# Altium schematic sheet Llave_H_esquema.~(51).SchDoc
size A4
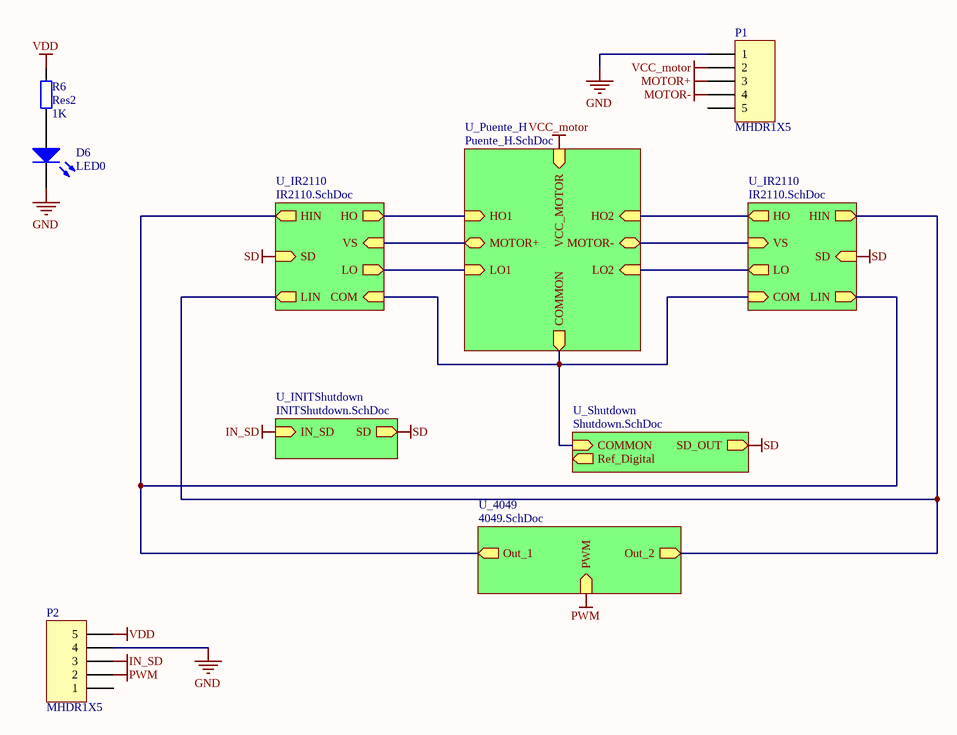
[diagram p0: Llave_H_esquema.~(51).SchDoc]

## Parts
D6  LED0  [CAPPR2.5-6.3X5]
P1  MHDR1X5  [MHDR1X5]
P2  MHDR1X5  [MHDR1X5]
R6  Res2  value 1K  [AXIAL-0.3]

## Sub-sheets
U_4049 = 4049.SchDoc: PWM (in), Out_1 (out), Out_2 (out)
U_INITShutdown = INITShutdown.SchDoc: IN_SD (in), SD (out)
U_IR2110 = IR2110.SchDoc: SD (in), HIN (out), LIN (out), HO (out), LO (out), VS (in), COM (in)
U_IR2110 = IR2110.SchDoc: SD (in), HIN (out), LIN (out), HO (out), LO (out), VS (in), COM (in)
U_Puente_H = Puente_H.SchDoc: HO1 (in), LO1 (in), HO2 (in), LO2 (in), MOTOR+ (bidir), MOTOR- (bidir), VCC_MOTOR (in), COMMON (out)
U_Shutdown = Shutdown.SchDoc: COMMON (in), SD_OUT (out), Ref_Digital (out)

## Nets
GND: D6.2(K) P1.1 P2.4
IN_SD: P2.3 ; sheet U_INITShutdown/IN_SD
MOTOR+: P1.3
MOTOR-: P1.4
PWM: P2.2 ; sheet U_4049/PWM
SD: sheet U_IR2110/SD, sheet U_IR2110/SD, sheet U_INITShutdown/SD, sheet U_Shutdown/SD_OUT
VCC_motor: P1.2 ; sheet U_Puente_H/VCC_MOTOR
VDD: P2.5 R6.2
NetD6_1: D6.1(A) R6.1
(unnamed): sheet U_IR2110/HIN, sheet U_IR2110/LIN, sheet U_4049/Out_1
(unnamed): sheet U_IR2110/LIN, sheet U_IR2110/HIN, sheet U_4049/Out_2  [a separate net that carries the same name]
(unnamed): sheet U_IR2110/HO, sheet U_Puente_H/HO1  [a separate net that carries the same name]
(unnamed): sheet U_IR2110/LO, sheet U_Puente_H/LO1  [a separate net that carries the same name]
(unnamed): sheet U_IR2110/VS, sheet U_Puente_H/MOTOR+  [a separate net that carries the same name]
(unnamed): sheet U_IR2110/COM, sheet U_IR2110/COM, sheet U_Puente_H/COMMON, sheet U_Shutdown/COMMON  [a separate net that carries the same name]
(unnamed): sheet U_IR2110/HO, sheet U_Puente_H/HO2  [a separate net that carries the same name]
(unnamed): sheet U_IR2110/LO, sheet U_Puente_H/LO2  [a separate net that carries the same name]
(unnamed): sheet U_IR2110/VS, sheet U_Puente_H/MOTOR-  [a separate net that carries the same name]

Not connected (* = marked no-connect by the designer): P1 5; P2 1

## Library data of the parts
D6 = LED0: Typical INFRARED GaAs LED
P1 P2 = MHDR1X5: Header, 5-Pin
R6 = Res2: Resistor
